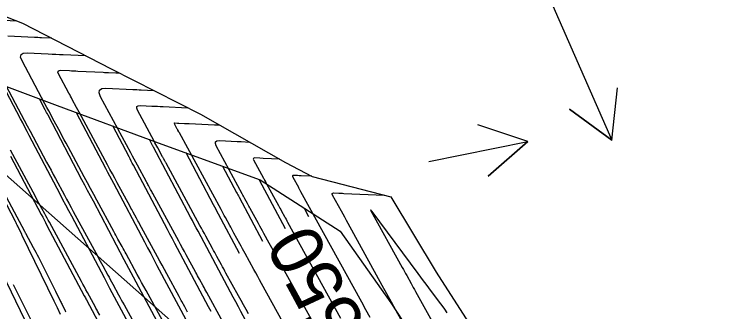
# Model space of a CAD drawing. Extents: x 954385 to 988206, y 1868364 to 1924553.
# Drawn here: x 957559.9 to 957642.4, y 1920301.8 to 1920335.7 of the extents above; entities that cross this region are included whole.
import ezdxf

# ---------------------------------------------------------------- set-up
doc = ezdxf.new("R2010")
doc.units = 0
for name, color, linetype in [('1', 7, 'Continuous'), ('Ex_Major Contours', 7, 'Continuous'), ('Ex_Minor Contours', 7, 'Continuous'), ('Perimeter', 7, 'Continuous'), ('Slopes', 7, 'Continuous')]:
    doc.layers.add(name, color=color, linetype=linetype)

msp = doc.modelspace()

# ---------------------------------------------------------------- linework, layer by layer
at = {"layer": '1'}
for points in [[(957450.815, 1920332.788), (957523.933, 1920382.247), (957528.249, 1920373.093), (957532.507, 1920363.9), (957536.678, 1920354.649), (957540.735, 1920345.321), (957544.536, 1920336.712), (957544.181, 1920336.46), (957544.363, 1920335.701), (957553.229, 1920329.626), (957564.727, 1920325.33), (957576.259, 1920321.058), (957587.884, 1920316.848), (957597.031, 1920310.962), (957602.817, 1920302.803), (957608.305, 1920294.443), (957613.907, 1920286.16), (957619.639, 1920277.964), (957625.387, 1920269.779), (957631.03, 1920261.523), (957636.615, 1920253.228), (957642.475, 1920245.119), (957647.904, 1920236.718)], [(957574.995, 1920296.511), (957570.758, 1920304.441), (957570.596, 1920304.743), (957570.435, 1920305.046), (957570.274, 1920305.348), (957570.114, 1920305.651), (957566.394, 1920312.67), (957566.06, 1920313.301), (957565.726, 1920313.933), (957565.393, 1920314.565), (957565.061, 1920315.198), (957561.551, 1920321.878), (957561.298, 1920322.359), (957561.046, 1920322.84), (957560.795, 1920323.322), (957560.544, 1920323.803), (957558.545, 1920327.64)], [(957577.337, 1920298.46), (957573.446, 1920305.741), (957573.183, 1920306.234), (957572.92, 1920306.727), (957572.658, 1920307.22), (957572.396, 1920307.713), (957568.865, 1920314.379), (957568.538, 1920314.996), (957568.211, 1920315.614), (957567.886, 1920316.232), (957567.56, 1920316.851), (957563.695, 1920324.208), (957563.613, 1920324.365), (957563.531, 1920324.521), (957563.449, 1920324.677), (957563.367, 1920324.834), (957562.718, 1920326.081)], [(957566.895, 1920324.527), (957570.246, 1920318.15), (957570.471, 1920317.722), (957570.696, 1920317.295), (957570.922, 1920316.868), (957571.148, 1920316.441), (957574.689, 1920309.757), (957575.047, 1920309.082), (957575.406, 1920308.408), (957575.765, 1920307.733), (957576.124, 1920307.06), (957579.678, 1920300.409)], [(957582.324, 1920301.789), (957582.02, 1920302.358), (957578.466, 1920309.009), (957578.178, 1920309.548), (957577.89, 1920310.088), (957577.603, 1920310.628), (957577.316, 1920311.169), (957573.43, 1920318.503), (957573.305, 1920318.739), (957573.181, 1920318.975), (957573.056, 1920319.212), (957572.931, 1920319.449), (957571.077, 1920322.978)], [(957589.318, 1920295.097), (957585.702, 1920301.807), (957585.408, 1920302.354), (957585.114, 1920302.901), (957584.82, 1920303.449), (957584.527, 1920303.996), (957580.807, 1920310.958), (957580.591, 1920311.363), (957580.375, 1920311.769), (957580.159, 1920312.175), (957579.944, 1920312.581), (957575.713, 1920320.565), (957575.689, 1920320.61), (957575.665, 1920320.656), (957575.641, 1920320.702), (957575.617, 1920320.747), (957575.259, 1920321.429)], [(957559.407, 1920319.548), (957562.917, 1920312.868), (957563.079, 1920312.56), (957563.241, 1920312.252), (957563.403, 1920311.945), (957563.566, 1920311.637), (957567.831, 1920303.589), (957567.89, 1920303.477), (957567.95, 1920303.364), (957568.01, 1920303.252), (957568.069, 1920303.14), (957572.653, 1920294.561)], [(957585.547, 1920308.419), (957583.149, 1920312.907), (957583.004, 1920313.178), (957582.86, 1920313.45), (957582.715, 1920313.721), (957582.571, 1920313.993), (957579.437, 1920319.907)], [(957565.126, 1920301.454), (957564.752, 1920302.222), (957564.378, 1920302.99), (957560.737, 1920310.493), (957560.713, 1920310.542), (957560.689, 1920310.592), (957560.237, 1920311.535), (957560.173, 1920311.667), (957560.108, 1920311.799), (957560.041, 1920311.93), (957559.973, 1920312.06), (957556.434, 1920318.797)], [(957583.614, 1920318.395), (957585.198, 1920315.405), (957585.271, 1920315.268), (957585.344, 1920315.13), (957585.417, 1920314.993), (957585.491, 1920314.856), (957588.175, 1920309.833)], [(957590.802, 1920311.247), (957587.832, 1920316.805), (957587.826, 1920316.817), (957587.791, 1920316.882)], [(957592.926, 1920313.604), (957593.43, 1920312.661)], [(957557.889, 1920307.293), (957561.535, 1920299.782)]]:
    msp.add_lwpolyline(points, dxfattribs=at)
at = {"layer": 'Ex_Major Contours'}
for points in [[(957579.62, 1920301.747), (957579.539, 1920301.895), (957579.457, 1920302.043), (957579.376, 1920302.191), (957579.295, 1920302.339), (957578.971, 1920302.932), (957578.89, 1920303.081), (957578.809, 1920303.229), (957578.728, 1920303.377), (957578.647, 1920303.525), (957577.228, 1920306.116), (957576.965, 1920306.597), (957576.702, 1920307.078), (957576.439, 1920307.56), (957576.177, 1920308.042), (957574.122, 1920311.824), (957574.034, 1920311.986), (957573.945, 1920312.149), (957573.856, 1920312.312), (957573.768, 1920312.474), (957573.413, 1920313.125), (957573.324, 1920313.287), (957573.236, 1920313.45), (957573.147, 1920313.613), (957573.059, 1920313.775), (957571.578, 1920316.501), (957571.302, 1920317.009), (957571.027, 1920317.518), (957570.752, 1920318.027), (957570.477, 1920318.537), (957567.247, 1920324.536), (957566.951, 1920325.085), (957566.458, 1920326.001), (957566.359, 1920326.184), (957566.261, 1920326.368), (957566.162, 1920326.551), (957566.064, 1920326.735), (957564.893, 1920328.929), (957564.822, 1920329.116), (957564.842, 1920329.247), (957564.951, 1920329.321), (957565.151, 1920329.337), (957566.13, 1920329.29), (957566.374, 1920329.278), (957566.619, 1920329.267), (957566.864, 1920329.255), (957567.108, 1920329.243), (957569.985, 1920329.105), (957570.136, 1920329.098), (957570.287, 1920329.091), (957570.437, 1920329.084), (957570.588, 1920329.077), (957571.445, 1920329.037), (957571.589, 1920329.03), (957571.876, 1920329.016)], [(957590.126, 1920319.195), (957588.26, 1920319.28), (957587.849, 1920319.299), (957587.301, 1920319.324), (957587.189, 1920319.315), (957587.128, 1920319.273), (957587.117, 1920319.2), (957587.157, 1920319.096), (957588.284, 1920317.022), (957588.312, 1920316.97), (957588.341, 1920316.918), (957588.37, 1920316.865), (957588.398, 1920316.813), (957588.513, 1920316.604), (957588.542, 1920316.551), (957588.57, 1920316.499), (957588.599, 1920316.447), (957588.627, 1920316.394), (957589.986, 1920313.907), (957590.072, 1920313.748), (957590.159, 1920313.59), (957590.246, 1920313.432), (957590.333, 1920313.274), (957590.683, 1920312.641), (957590.77, 1920312.483), (957590.857, 1920312.325), (957590.944, 1920312.167), (957591.031, 1920312.009), (957597.073, 1920301.036)], [(957559.701, 1920304.894), (957559.967, 1920304.365), (957560.233, 1920303.836), (957560.499, 1920303.307), (957562.158, 1920300.003)]]:
    msp.add_lwpolyline(points, dxfattribs=at)
at = {"layer": 'Ex_Minor Contours'}
for points in [[(957554.992, 1920335.234), (957560.082, 1920334.983)], [(957564.13, 1920332.987), (957562.933, 1920333.044), (957562.734, 1920333.054), (957562.535, 1920333.064), (957562.335, 1920333.073), (957562.136, 1920333.083), (957559.088, 1920333.229)], [(957576.742, 1920300.785), (957574.877, 1920304.19), (957574.625, 1920304.65), (957574.374, 1920305.11), (957574.123, 1920305.571), (957573.872, 1920306.031), (957572.602, 1920308.369), (957572.486, 1920308.582), (957572.37, 1920308.796), (957572.253, 1920309.009), (957572.137, 1920309.222), (957571.672, 1920310.075), (957571.555, 1920310.289), (957571.439, 1920310.502), (957571.323, 1920310.715), (957571.207, 1920310.929), (957569.266, 1920314.503), (957568.904, 1920315.17), (957568.542, 1920315.838), (957568.182, 1920316.505), (957567.821, 1920317.173), (957565.98, 1920320.594), (957565.759, 1920321.003), (957565.539, 1920321.412), (957565.318, 1920321.822), (957565.098, 1920322.231), (957564.216, 1920323.868), (957563.996, 1920324.278), (957563.776, 1920324.687), (957563.557, 1920325.097), (957563.338, 1920325.507), (957560.719, 1920330.41), (957560.562, 1920330.829), (957560.606, 1920331.121), (957560.851, 1920331.285), (957561.297, 1920331.323), (957563.72, 1920331.206), (957564.149, 1920331.186), (957564.577, 1920331.165), (957565.005, 1920331.145), (957565.433, 1920331.124), (957568.003, 1920331.001)], [(957557.412, 1920330.268), (957560.611, 1920324.279), (957560.951, 1920323.643), (957561.292, 1920323.006), (957561.633, 1920322.371), (957561.975, 1920321.735), (957563.521, 1920318.864), (957563.775, 1920318.394), (957564.028, 1920317.923), (957564.282, 1920317.452), (957564.535, 1920316.981), (957565.549, 1920315.098), (957565.803, 1920314.627), (957566.057, 1920314.157), (957566.312, 1920313.687), (957566.567, 1920313.217), (957569.355, 1920308.082), (957569.499, 1920307.818), (957569.643, 1920307.554), (957569.786, 1920307.29), (957569.93, 1920307.026), (957570.507, 1920305.97), (957570.651, 1920305.707), (957570.794, 1920305.443), (957570.938, 1920305.179), (957571.082, 1920304.914), (957571.732, 1920303.717), (957571.889, 1920303.429), (957572.045, 1920303.142), (957572.202, 1920302.855), (957572.359, 1920302.568), (957574.837, 1920298.045)], [(957583.691, 1920300.561), (957581.808, 1920303.97), (957581.703, 1920304.161), (957581.598, 1920304.352), (957581.493, 1920304.543), (957581.388, 1920304.735), (957580.97, 1920305.5), (957580.866, 1920305.692), (957580.761, 1920305.883), (957580.657, 1920306.074), (957580.552, 1920306.265), (957579.462, 1920308.255), (957579.246, 1920308.65), (957579.03, 1920309.046), (957578.814, 1920309.442), (957578.598, 1920309.838), (957575.642, 1920315.278), (957575.581, 1920315.39), (957575.52, 1920315.502), (957575.459, 1920315.614), (957575.398, 1920315.726), (957575.154, 1920316.174), (957575.093, 1920316.286), (957575.032, 1920316.398), (957574.971, 1920316.51), (957574.91, 1920316.622), (957573.891, 1920318.498), (957573.701, 1920318.849), (957573.511, 1920319.199), (957573.322, 1920319.549), (957573.133, 1920319.9), (957569.681, 1920326.31), (957569.51, 1920326.761), (957569.556, 1920327.075), (957569.82, 1920327.252), (957570.3, 1920327.293), (957573.353, 1920327.15), (957573.592, 1920327.139), (957573.832, 1920327.127), (957574.072, 1920327.116), (957574.312, 1920327.105), (957575.75, 1920327.037)], [(957586.572, 1920301.527), (957586.289, 1920302.041), (957586.006, 1920302.554), (957585.722, 1920303.068), (957585.439, 1920303.581), (957583.996, 1920306.194), (957583.867, 1920306.428), (957583.738, 1920306.662), (957583.61, 1920306.896), (957583.482, 1920307.13), (957582.97, 1920308.068), (957582.842, 1920308.302), (957582.714, 1920308.537), (957582.585, 1920308.771), (957582.457, 1920309.005), (957581.696, 1920310.394), (957581.527, 1920310.704), (957581.357, 1920311.014), (957581.188, 1920311.324), (957581.02, 1920311.634), (957577.163, 1920318.733), (957577.129, 1920318.794), (957577.096, 1920318.856), (957577.062, 1920318.917), (957577.029, 1920318.978), (957576.895, 1920319.223), (957576.862, 1920319.285), (957576.828, 1920319.346), (957576.795, 1920319.407), (957576.762, 1920319.469), (957576.204, 1920320.496), (957576.1, 1920320.688), (957575.996, 1920320.879), (957575.892, 1920321.071), (957575.789, 1920321.263), (957573.899, 1920324.773), (957573.805, 1920325.02), (957573.83, 1920325.191), (957573.975, 1920325.289), (957574.237, 1920325.311), (957575.527, 1920325.251), (957575.849, 1920325.235), (957576.171, 1920325.22), (957576.494, 1920325.205), (957576.816, 1920325.19), (957579.623, 1920325.058)], [(957592.312, 1920297.296), (957588.058, 1920305.021), (957587.841, 1920305.416), (957587.623, 1920305.811), (957587.405, 1920306.206), (957587.187, 1920306.601), (957586.184, 1920308.417), (957586.031, 1920308.694), (957585.879, 1920308.971), (957585.727, 1920309.249), (957585.575, 1920309.526), (957584.91, 1920310.743), (957584.788, 1920310.967), (957584.666, 1920311.191), (957584.543, 1920311.415), (957584.421, 1920311.639), (957583.93, 1920312.534), (957583.808, 1920312.758), (957583.685, 1920312.982), (957583.563, 1920313.206), (957583.441, 1920313.43), (957578.683, 1920322.188), (957578.66, 1920322.23), (957578.619, 1920322.305), (957578.516, 1920322.494), (957578.498, 1920322.527), (957578.48, 1920322.56), (957578.462, 1920322.593), (957578.444, 1920322.627), (957578.116, 1920323.236), (957578.1, 1920323.279), (957578.104, 1920323.308), (957578.129, 1920323.325), (957578.175, 1920323.329), (957578.455, 1920323.316), (957578.623, 1920323.308), (957579.27, 1920323.278), (957579.397, 1920323.272), (957579.524, 1920323.266), (957579.65, 1920323.26), (957579.777, 1920323.254), (957582.694, 1920323.121), (957583.231, 1920323.097)], [(957594.692, 1920299.166), (957589.545, 1920308.515), (957589.392, 1920308.792), (957589.24, 1920309.068), (957589.087, 1920309.345), (957588.935, 1920309.621), (957588.324, 1920310.727), (957588.171, 1920311.004), (957588.019, 1920311.281), (957587.867, 1920311.558), (957587.716, 1920311.835), (957586.769, 1920313.569), (957586.693, 1920313.707), (957586.618, 1920313.845), (957586.542, 1920313.983), (957586.467, 1920314.121), (957586.164, 1920314.673), (957586.089, 1920314.812), (957586.013, 1920314.95), (957585.938, 1920315.088), (957585.863, 1920315.226), (957582.889, 1920320.698), (957582.783, 1920320.974), (957582.811, 1920321.167), (957582.972, 1920321.276), (957583.267, 1920321.302), (957585.284, 1920321.21), (957585.749, 1920321.189), (957586.678, 1920321.146)], [(957569.592, 1920301.403), (957569.344, 1920301.861), (957569.281, 1920301.975), (957569.219, 1920302.089), (957569.157, 1920302.204), (957569.094, 1920302.318), (957568.189, 1920303.977), (957568.018, 1920304.291), (957567.846, 1920304.606), (957567.675, 1920304.921), (957567.504, 1920305.235), (957563.837, 1920311.987), (957563.704, 1920312.231), (957563.572, 1920312.476), (957563.44, 1920312.72), (957563.308, 1920312.965), (957562.649, 1920314.188), (957562.386, 1920314.678), (957562.254, 1920314.922), (957559.404, 1920320.215)], [(957556.498, 1920319.316), (957560.997, 1920310.962), (957561.067, 1920310.832), (957561.087, 1920310.795), (957561.107, 1920310.758), (957561.994, 1920309.124), (957562.144, 1920308.845), (957562.292, 1920308.565), (957562.438, 1920308.283), (957562.581, 1920308.001), (957564.065, 1920305.043), (957564.299, 1920304.578), (957564.532, 1920304.113), (957565.121, 1920302.939), (957565.177, 1920302.828), (957565.232, 1920302.717), (957565.288, 1920302.606), (957565.344, 1920302.495), (957565.672, 1920301.843), (957565.686, 1920301.814), (957565.715, 1920301.756)], [(957593.779, 1920317.239), (957592.577, 1920317.293), (957592.364, 1920317.302), (957592.151, 1920317.312), (957591.725, 1920317.331), (957591.638, 1920317.324), (957591.591, 1920317.292), (957591.583, 1920317.235), (957591.614, 1920317.154), (957592.256, 1920315.979), (957592.277, 1920315.939), (957592.299, 1920315.899), (957592.321, 1920315.86), (957592.343, 1920315.82), (957592.43, 1920315.661), (957592.474, 1920315.582), (957592.518, 1920315.503), (957599.453, 1920302.907), (957599.931, 1920302.04), (957600.409, 1920301.175)], [(957603.96, 1920300.937), (957603.427, 1920301.896), (957602.894, 1920302.856), (957602.364, 1920303.816), (957601.834, 1920304.777), (957597.935, 1920311.859), (957597.742, 1920312.208), (957597.55, 1920312.557), (957597.357, 1920312.907), (957597.164, 1920313.256), (957596.145, 1920315.1), (957596.102, 1920315.209), (957596.113, 1920315.285), (957596.176, 1920315.328), (957596.292, 1920315.338), (957596.864, 1920315.313), (957597.006, 1920315.306), (957597.149, 1920315.3), (957597.292, 1920315.294), (957597.435, 1920315.287), (957602.044, 1920315.085)], [(957609.261, 1920301.668), (957608.958, 1920302.074), (957608.655, 1920302.48), (957608.353, 1920302.885), (957607.141, 1920304.508), (957606.838, 1920304.913), (957606.536, 1920305.319), (957606.234, 1920305.726), (957605.932, 1920306.132), (957600.688, 1920313.205), (957600.583, 1920313.347), (957600.578, 1920313.352), (957600.572, 1920313.356), (957600.566, 1920313.358), (957600.559, 1920313.359), (957600.507, 1920313.362), (957600.505, 1920313.361), (957600.505, 1920313.359), (957604.114, 1920306.827), (957604.241, 1920306.598), (957604.367, 1920306.369), (957604.494, 1920306.14), (957604.62, 1920305.911), (957605.125, 1920304.994), (957605.251, 1920304.765), (957605.378, 1920304.536), (957605.504, 1920304.307), (957605.632, 1920304.078), (957610.02, 1920296.197)]]:
    msp.add_lwpolyline(points, dxfattribs=at)
at = {"layer": 'Perimeter'}
msp.add_lwpolyline([(957549.482, 1920339.164), (957560.756, 1920334.717), (957570.908, 1920329.511), (957581.076, 1920324.316), (957590.795, 1920318.817), (957593.82, 1920317.217), (957602.826, 1920314.882), (957607.972, 1920306.291), (957613.378, 1920297.874), (957618.787, 1920289.46), (957622.216, 1920283.607), (957624.02, 1920280.927), (957629.264, 1920272.401), (957634.701, 1920264.006), (957640.225, 1920255.67), (957645.505, 1920247.168)], dxfattribs=at)
at = {"layer": 'Slopes'}
for points in [[(957607.131, 1920368.928), (957628.045, 1920321.35), (957623.207, 1920324.9), (957628.045, 1920321.35), (957628.7, 1920327.314)], [(957607.131, 1920318.928), (957618.431, 1920321.204), (957613.929, 1920317.237), (957618.431, 1920321.204), (957612.745, 1920323.119)], [(957557.131, 1920318.928), (957602.153, 1920279.081), (957596.274, 1920280.278), (957602.153, 1920279.081), (957600.25, 1920284.771)]]:
    msp.add_lwpolyline(points, dxfattribs=at)

# ---------------------------------------------------------------- texts
at = {"layer": '1'}
msp.add_text('550', height=6, rotation=118.28545, dxfattribs=at).set_placement((957600.044, 1920300.403))

doc.saveas('drawing.dxf')
